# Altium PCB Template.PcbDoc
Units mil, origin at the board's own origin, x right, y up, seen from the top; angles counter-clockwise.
Board outline 6000 x 4000 mil, 2 copper layers (Top Layer, Bottom Layer); 26 components, 24 nets, 78 pads, 0 vias.
Unrouted connection lines stored in the file: 46.
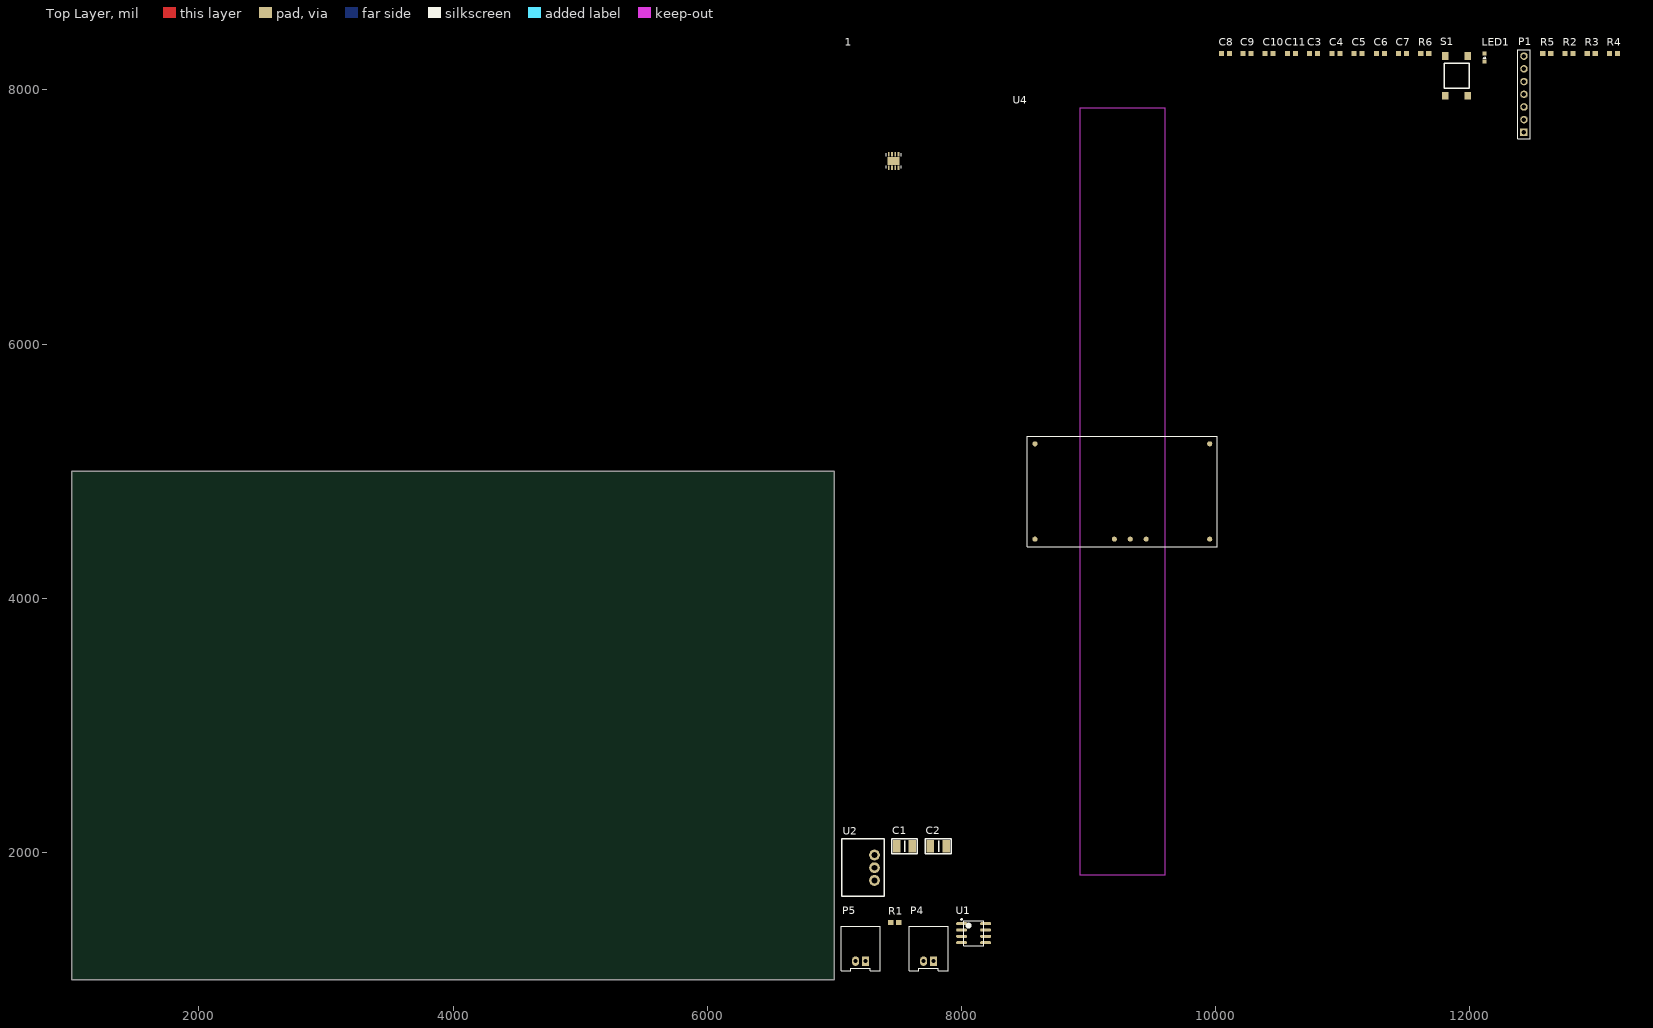
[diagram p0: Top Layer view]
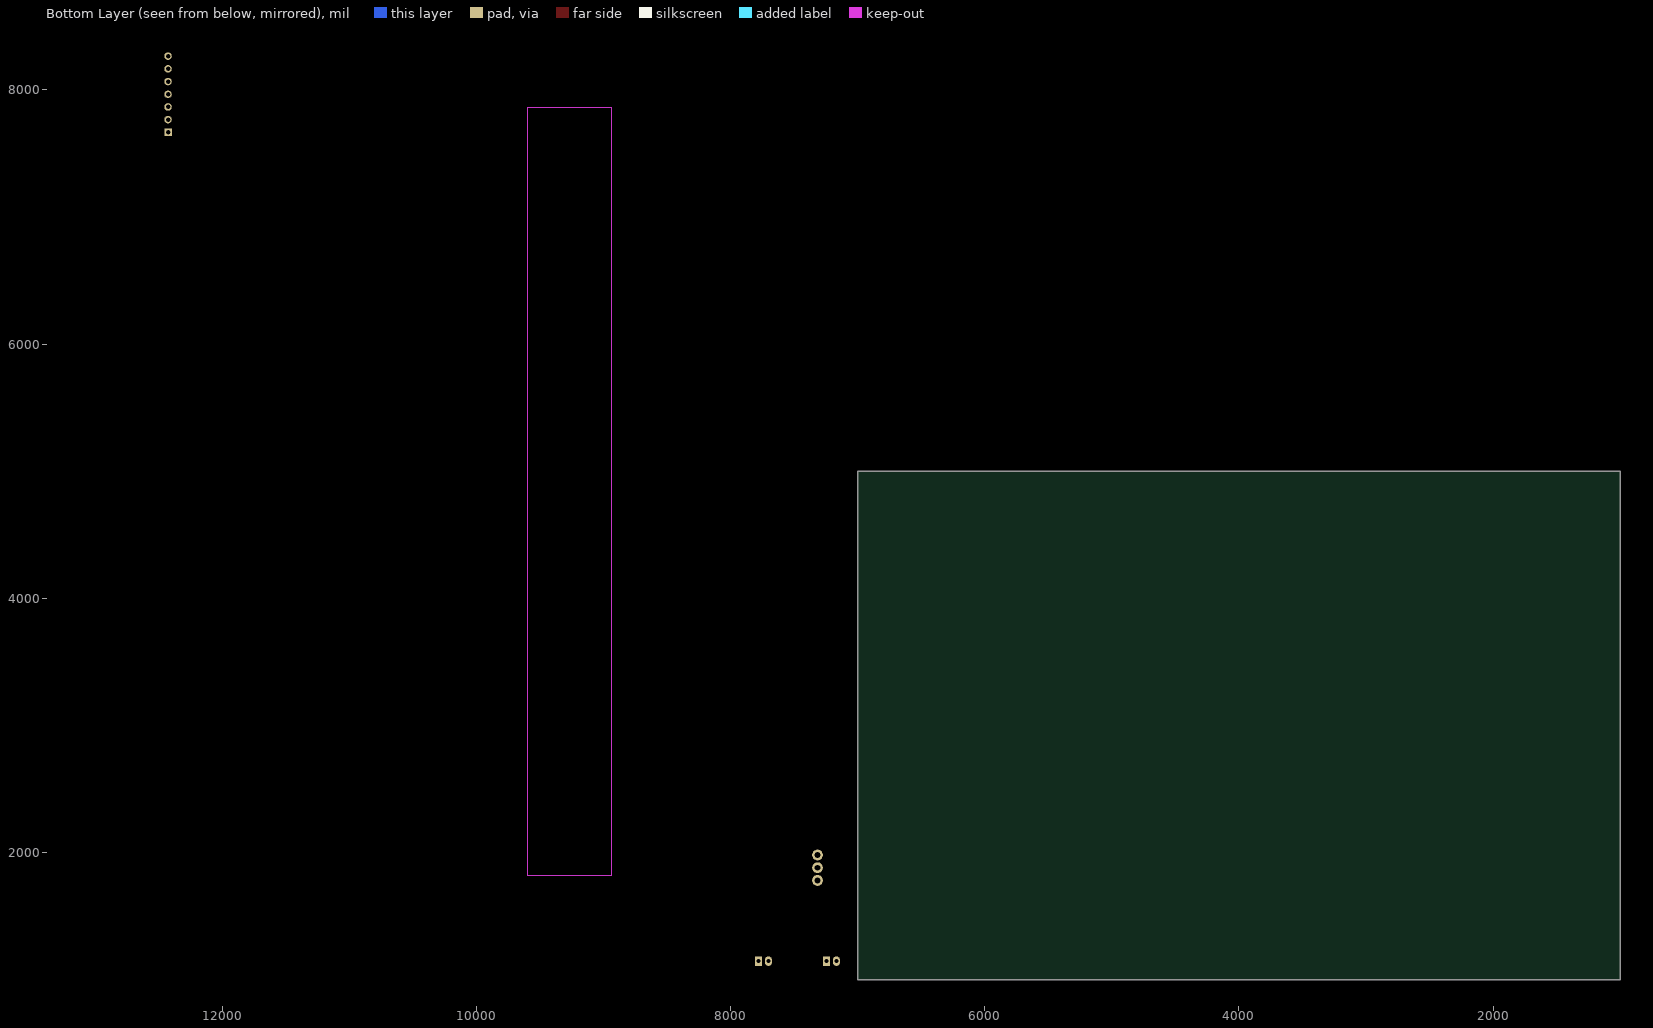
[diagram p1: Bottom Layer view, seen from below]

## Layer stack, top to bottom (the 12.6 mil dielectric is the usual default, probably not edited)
Top Solder: solder mask 0.4, Solder Resist, Dk 3.5
Top Layer: signal copper 1.4
Dielectric 1: dielectric 12.6, FR-4, Dk 4.8
Bottom Layer: signal copper 1.4
Bottom Solder: solder mask 0.4, Solder Resist, Dk 3.5

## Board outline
1000,1000 7000,1000 7000,5000 1000,5000

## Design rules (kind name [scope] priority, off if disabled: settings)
Clearance [All] p1: gap=10 ignorepadtopadclearanceinfootprint=FALSE except(0: Arc-Hole Track-Hole SMDPad-Hole THPad-Hole Via-Hole Fill-Hole Poly-Hole Region-Hole Text-Hole)
PolygonConnect [All] p1: connectstyle=Relief reliefconductorwidth=10 reliefentries=4 polygonreliefangle="90 Angle" airgapwidth=10
RoomDefinition Tiva_C_Base [InComponentClass('Tiva_C_Base')] p1: confinementstyle=ConfineIn formatcopy=TRUE lockcomponents=FALSE outline 7045,1250 13200,1250 13200,8425 7045,8425
RoomDefinition RECOM_24to3v3 [InComponentClass('RECOM_24to3v3')] p2: confinementstyle=ConfineIn formatcopy=TRUE lockcomponents=FALSE outline 7045,1250 11540,1250 11540,8425 7045,8425
RoomDefinition CAN_Connections [InComponentClass('CAN_Connections')] p3: confinementstyle=ConfineIn formatcopy=TRUE lockcomponents=FALSE outline 7045,1060 13200,1060 13200,8425 7045,8425
RoutingVias [All] p1: holewidth=28 width=50 viastyle="Through Hole" minholewidth=28 minwidth=50 maxholewidth=28 maxwidth=50
SolderMaskExpansion [All] p1: expansion=4
Width [All] p1: maxlimit=10 minlimit=10 preferedwidth=10
30 further rules are at their usual default settings.

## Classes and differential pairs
component class RECOM_24to3v3: C1 C2 C6 L? U2
component class Tiva_C_Base: 1 C1 C2 C3 C4 C5 C6 C7 C8 C9 C10 C11 C? LED1 P1 R1 R2 R3 R4 R5 R6 R? S1 U4
component class CAN_Connections: P4 P5 R1 U1

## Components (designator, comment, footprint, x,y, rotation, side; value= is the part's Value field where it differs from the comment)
1 "MCP4131-XXXX/MF" DFN8_3x3MC 7465,7440 r90 top value=Value
C1 "CAP1210" CAP1210 7615,2050 r0 top value=10uF
C2 "CAP1210" CAP1210 7880,2050 r0 top value=10uF
C3 "Cap" CAPC0603 10770,8285 r0 top value=0.1uF
C4 "Cap" CAPC0603 10945,8285 r0 top value=0.1uF
C5 "Cap" CAPC0603 11120,8285 r0 top value=0.1uF
C6 "Cap" CAPC0603 11295,8285 r0 top value=0.1uF
C7 "Cap" CAPC0603 11470,8285 r0 top value=2.0uF
C8 "Cap" CAPC0603 10075,8285 r0 top value=0.1uF
C9 "Cap" CAPC0603 10245,8285 r0 top value=0.1uF
C10 "Cap" CAPC0603 10420,8285 r0 top value=1.0uF
C11 "Cap" CAPC0603 10595,8285 r0 top value=2.2uF
LED1 "LED" LED0603 12115,8255 r90 top
P1 "Header 7" HDR1X7 12425,7665 r90 top
P4 "2-pin Horz Sherlock" MOLEX-HDR-1X2-SHERLOCK-HORZ 7780,1145 r0 top
P5 "2-pin Horz Sherlock" MOLEX-HDR-1X2-SHERLOCK-HORZ 7245,1145 r0 top
R1 "Res" RES0603 7475,1450 r0 top value=120
R2 "Res" RES0603 12780,8285 r0 top value=10k
R3 "Res" RES0603 12955,8285 r0 top value=10k
R4 "Res" RES0603 13130,8285 r0 top value=10k
R5 "Res" RES0603 12605,8285 r0 top value=1k
R6 "Res" RES0603 11645,8285 r0 top value=10k
S1 "Button" PTS645xxxxSMTR92 11895,8110 r90 top
U1 "SN65HVD230DR" SOIC-8pin 8095,1365 r0 top
U2 "R-78C3.3-1.0" R-78C3.3-1.0 7315,1780 r90 top
U4 "Part Number: ptn78020w_euk_7" EUK7 9265,4840 r90 top value=Value

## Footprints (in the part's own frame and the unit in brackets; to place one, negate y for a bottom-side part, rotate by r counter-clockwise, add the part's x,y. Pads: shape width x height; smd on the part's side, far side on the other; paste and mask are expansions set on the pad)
CAP1210 [mm]
  rect 1.5x2.5 smd: 1(-0.02,0) 2(-3.2,0)
  silkscreen extent -4.2,-1.48 0.97,1.48, body extent -3.22,-1.25 0,1.26, height 2.5
CAPC0603 [mm] "Chip Capacitor, 2-Leads, Body 1.60x0.80mm, IPC Medium Density"
  rect 1x0.95 smd: 1(-0.8,0) 2(0.8,0)
  body extent -0.88,-0.48 0.87,0.48, height 0.8
DFN8_3x3MC [mil]
  rect 34x14 smd: 1(-54.06,38.39) 2(-54.06,12.8) 3(-54.06,-12.8) 4(-54.06,-38.39) 5(54.06,-38.39) 6(54.06,-12.8) 7(54.06,12.8) 8(54.06,38.39)
  rect 63x95 smd: 9(0,0)
  silkscreen extent -59,-59 59,59, body extent 0,0 10,10, height 10
EUK7 [mil]
  round 40 smd: 1(375,-687.5) 2(-375,-687.5) 3(-375,-187.5) 4(-375,-62.5) 5(-375,62.5) 6(-375,687.5) 7(375,687.5)
  Keep-Out Layer region: -3020,-332.5 -3020,332.5 3020,332.5 3020,-332.5
  silkscreen extent -435,-748 435,748, body extent 0,0 10,10, height 10
HDR1X7 [mm] "Connector; Header; 7 Position"
  rect 1.5x1.5 hole 0.9: 1(0,0)
  round 1.5 hole 0.9: 2(2.54,0) 3(5.08,0) 4(7.62,0) 5(10.16,0) 6(12.7,0) 7(15.24,0)
  silkscreen extent -1.27,-1.27 16.51,1.27
LED0603 [mm] "Chip LED, 2-Leads, Body 1.60x0.80mm, IPC Medium Density"
  rect 0.8x0.8 smd: A(-0.825,0) C(0.825,0)
  silkscreen extent -0.13,-0.25 0.12,0.25, body extent -0.88,-0.48 0.87,0.47, height 0.8
MOLEX-HDR-1X2-SHERLOCK-HORZ [mm]
  rect 1.397x1.905 hole 0.8: 1(0,0)
  oval 1.397x1.905 hole 0.8: 2(-2,0)
  silkscreen extent -4.83,-1.91 2.92,6.98, body extent -4.83,-1.91 2.87,8.59, height 5.54
PTS645xxxxSMTR92 [mm] "PTS645 Series SMT 6 mm Tactile Switch"
  rect 1.555x1.3 smd: A(-3.975,2.25) A(3.975,2.25) B(-3.975,-2.25) B(3.975,-2.25)
  silkscreen extent -2.5,-2.5 2.5,2.5, body extent -3,-3 3,3, height 4.5
R-78C3.3-1.0 [mm] "CONV DC/DC 1A 3.3V OUT SIP VERT"
  round 2.15 hole 1.15: 1(0,0) 2(2.54,0) 3(5.08,0)
  silkscreen extent -3.21,-2 8.29,6.5, body extent -3.3,-2.03 8.38,6.6, height 10.4
RES0603 [mm] "Chip Resistor, 2-Leads, Body 1.60x0.80mm, IPC Medium Density"
  rect 1.05x1 smd: 1(-0.8,0) 2(0.8,0)
  body extent -0.88,-0.48 0.87,0.47, height 0.8
SOIC-8pin [mm] "For 296-1345-1-ND"
  oval 2.2x0.6 smd: 1(-2.4,1.905) 2(-2.4,0.635) 3(-2.4,-0.635) 4(-2.4,-1.905) 5(2.4,-1.905) 6(2.4,-0.635) 7(2.4,0.635) 8(2.4,1.905)
  silkscreen extent -2.52,-2.5 2,2.88, body extent -2,-2.5 2,2.5, height 1.75

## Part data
1: "No Description Available"
C1 C2: "CAP CER 10UF 50V 20% X5R 1210", Supplier Part Number 1=CGA6P1X7R1N106K250AC
C3 C4 C5 C6 C7 C8 C9 C10 C11: Supplier Part Number 1=1276-1000-1-ND
LED1: Color=Green, Supplier Part Number 1=754-1122-1-ND
P1: "Header, 7-Pin"
P4 P5: library part MOLEX-HDR-1x2-SHERLOCK_RA, "Header, Molex, 2mm Pitch Sherlock Header, Single Row, Horizontal, 2 Circuits, Length 3.3mm,  0353630260", Manufacturer="Molex Inc", Manufacturer Part Number=0353630260, Supplier Part Number 1=WM18931-ND
R1 R2 R3 R4 R5 R6: Supplier Part Number 1=RMCF0603JT10K0CT-ND
S1: "SPST Button", Supplier Part Number 1=CKN9087CT-ND
U1: "IC TXRX CAN 1MBPS 3.3V 8SOIC", Supplier Part Numbe 1=296-11654-1-ND
U2: "CONV DC/DC 1A 3.3V OUT SIP VERT", Supplier Part Number 1=945-1394-5-ND
U4: library part PTN78020W_EUK_7, "6-A Wide-Input Voltage Adjustable Switching Regulator", Manufacturer="Texas Instruments", Manufacturer_Part_Number=ptn78020w_euk_7, PACKAGE_DESIGNATOR=EUK

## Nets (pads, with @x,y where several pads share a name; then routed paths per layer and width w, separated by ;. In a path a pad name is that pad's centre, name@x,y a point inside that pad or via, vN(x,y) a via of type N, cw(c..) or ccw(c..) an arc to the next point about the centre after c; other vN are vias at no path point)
24V: C1.1
CAN0_RX: U1.4
CAN0_TX: 
CAN_TX: U1.1
CANH: P4.2 P5.2 R1.2 U1.7
CANL: P4.1 P5.1 R1.1 U1.6
GND: C1.2 C2.2 C3.2 C4.2 C5.2 C6.2 C7.2 C8.2 C9.2 C10.2 C11.2 LED1.C P1.7 R6.2 S1.B U1.2 U1.8 U2.2
Net1_6: 1.6 U4.4
Net1_7: 1.7 U4.1
NetC2_1: C2.1 U2.1
NetLED1_A: LED1.A R5.2
RST_N: P1.5 R2.2 S1.A
SPIChipSelect: 
SPICLK: 
SPIRx: 
SPITx: 
TCK/SWCLK: P1.1 R3.2
TDI: P1.4
TDO/SWO: P1.3 R6.1
TMS/SWDIO: P1.2 R4.2
V0: U4.2
V1: 
VDD: C3.1 C4.1 C5.1 C6.1 C7.1 P1.6 R2.1 R3.1 R4.1 R5.1 U1.3 U2.3
VDDC: C8.1 C9.1 C10.1 C11.1
pads on no net: 1.1 1.2 1.3 1.4 1.5 1.8 1.9 U1.5 U4.3 U4.5 U4.6 U4.7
